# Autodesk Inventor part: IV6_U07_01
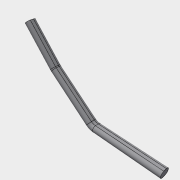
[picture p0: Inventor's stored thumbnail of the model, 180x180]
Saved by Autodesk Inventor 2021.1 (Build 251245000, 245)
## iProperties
Company: Autodesk, Inc.
Shininess: 64.0
Length Units: 11269
Angle Units: 11279
Time Units: 11290
Mass Units: 11283
Length Display Precision: 3
Angle Display Precision: 2
Compacted: True
Part Number: IV6_U07_01
Document SubType Name: Modeling
Created: 2002-09
Project: IV6 What's New
Description: SHIFT LEVER, GEAR-PPST
Density: 1 g/cm^3
Material: Generic
Appearance: Default
Density: 0.0
Volumn: 0.0
Area: 0.0
PropertySet Name: Model Information
Control State: 0
Master: False
Checked Out: False
Title: IV6_U07_01
Subject: IV6 What's New
Revision Number: 1
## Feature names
1. Sweep1
2. Hole1
## Parameters: d0 = 117.7 mm, d1 = 98.688 mm, d2 = 75.697 mm, d3 = 18 mm, d6 = 11.5 mm, d7 = 17 mm, d8 = 0, d9 = 3 mm, d10 = 4.917 mm, d11 = 16 mm, d12 = 6 mm, d13 = 2 mm, d14 = 45 deg, d15 = 21 mm, d16 = 118 deg, d17 = 0
